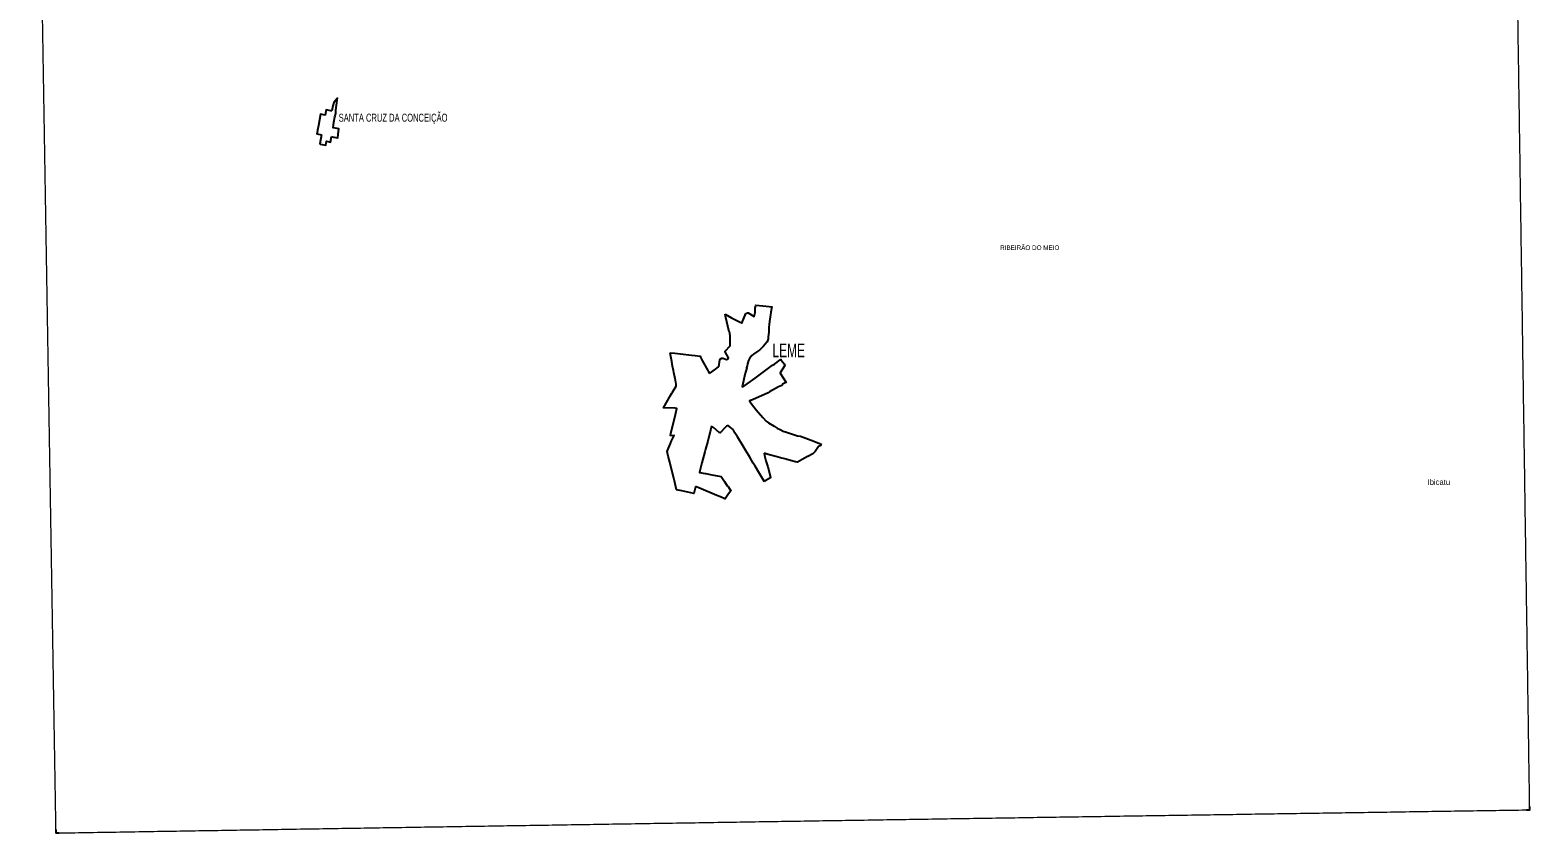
# Model space of a CAD drawing. Extents: x 241.9 to 268.1, y 7537.3 to 7565.4.
# Drawn here: x 241.88 to 268.11, y 7537.34 to 7551.39 of the extents above; entities that cross this region are included whole.
import ezdxf
from ezdxf.enums import TextEntityAlignment as Align

# ---------------------------------------------------------------- set-up
doc = ezdxf.new("R2010")
doc.units = 0
doc.header["$LTSCALE"] = 0.032
doc.linetypes.add('LONG_DASHED', pattern=[7.5, 6, -1.5])
for name, color, linetype, lineweight in [('41', 7, 'Continuous', 25), ('5', 7, 'LONG_DASHED', 13), ('63', 7, 'Continuous', 13)]:
    doc.layers.add(name, color=color, linetype=linetype, lineweight=lineweight)
doc.layers.add('61', color=7, linetype='Continuous')

msp = doc.modelspace()

# ---------------------------------------------------------------- linework, layer by layer
at = {"layer": '41'}
for points in [[(247.158, 7549.9711), (247.1423, 7549.9739), (247.0586, 7549.9889), (247.0416, 7549.8997), (246.9566, 7549.914), (246.9398, 7549.813), (246.9224, 7549.7189), (246.9078, 7549.6322), (246.9005, 7549.5936)], [(247.2292, 7549.9584), (247.2252, 7549.9827), (247.2514, 7550.157), (247.2544, 7550.1933), (247.1928, 7550.1205), (247.1731, 7550.0581), (247.158, 7549.9711)], [(247.2692, 7549.5651), (247.2766, 7549.6049), (247.2772, 7549.6582), (247.2513, 7549.6662), (247.1788, 7549.6778), (247.195, 7549.7748), (247.2115, 7549.8705)], [(247.2115, 7549.8705), (247.2261, 7549.9284), (247.2292, 7549.9584)], [(246.9005, 7549.5936), (246.897, 7549.5735), (246.9018, 7549.5702), (246.9774, 7549.556)], [(246.9774, 7549.556), (246.9477, 7549.3966), (246.9507, 7549.3926), (247.0543, 7549.3731), (247.0661, 7549.4409), (247.1354, 7549.4222), (247.1525, 7549.5231)], [(247.1525, 7549.5231), (247.1948, 7549.5152), (247.263, 7549.5023), (247.2692, 7549.5651)], [(253.9249, 7545.4932), (253.9436, 7545.6145), (253.9525, 7545.6292), (253.98, 7545.6484), (253.9977, 7545.6484), (254.0581, 7545.6246), (254.0845, 7545.6286), (254.0909, 7545.6366), (254.0933, 7545.6534), (254.0679, 7545.707), (254.0384, 7545.7591), (254.0375, 7545.7663), (254.1223, 7545.8648), (254.1272, 7545.8761), (254.1232, 7546.0246), (254.1173, 7546.0878), (254.1101, 7546.1062), (254.0421, 7546.3783), (254.0382, 7546.4182)], [(254.0382, 7546.4182), (254.1485, 7546.3511), (254.3125, 7546.2678), (254.328, 7546.2587), (254.3971, 7546.4281)], [(254.3971, 7546.4281), (254.4272, 7546.4389), (254.4378, 7546.4386), (254.5448, 7546.3759), (254.5648, 7546.4474)], [(254.5648, 7546.4474), (254.5621, 7546.4767), (254.5645, 7546.5191), (254.5756, 7546.5724), (254.6955, 7546.5598)], [(254.6955, 7546.5598), (254.8085, 7546.5479), (254.8557, 7546.5465), (254.8388, 7546.4513), (254.8303, 7546.4057)], [(254.8303, 7546.4057), (254.823, 7546.3706), (254.8178, 7546.3259), (254.8091, 7546.2404), (254.8036, 7546.1812), (254.7992, 7546.0986), (254.7899, 7546.0212)], [(254.7899, 7546.0212), (254.788, 7545.9853), (254.7797, 7545.947), (254.7701, 7545.9334), (254.7685, 7545.9238), (254.7077, 7545.8566), (254.6413, 7545.791), (254.6093, 7545.7662), (254.5349, 7545.7182), (254.5045, 7545.6926), (254.4645, 7545.6422), (254.4445, 7545.6038), (254.4261, 7545.5462), (254.4192, 7545.5146)], [(253.1383, 7545.3981), (253.1314, 7545.4308), (253.1187, 7545.5038), (253.1048, 7545.5855), (253.0838, 7545.7053), (253.0781, 7545.7416)], [(253.0781, 7545.7416), (253.1568, 7545.7362), (253.2542, 7545.7219), (253.4494, 7545.7017)], [(253.4494, 7545.7017), (253.5109, 7545.6953), (253.5974, 7545.6835), (253.6065, 7545.6637)], [(253.6065, 7545.6637), (253.6368, 7545.6058), (253.6586, 7545.5664), (253.7637, 7545.3763)], [(254.3395, 7545.1389), (254.5613, 7545.295), (254.8677, 7545.5222), (254.9005, 7545.5422), (254.9989, 7545.6158), (255.0061, 7545.6254), (255.0141, 7545.623), (255.0133, 7545.6198), (255.0531, 7545.5728), (255.0708, 7545.5453), (255.0806, 7545.5188), (254.9997, 7545.3918), (255.0013, 7545.383), (255.1031, 7545.2212), (255.0746, 7545.2094), (255.0392, 7545.1888), (255.0293, 7545.1694)], [(253.1052, 7545.0338), (253.118, 7545.0534), (253.178, 7545.159), (253.1812, 7545.1902), (253.178, 7545.1934), (253.1668, 7545.263), (253.1621, 7545.2851), (253.1383, 7545.3981)], [(253.7637, 7545.3763), (253.8666, 7545.4554), (253.9204, 7545.4926), (253.9249, 7545.4932)], [(254.4192, 7545.5146), (254.4113, 7545.4781), (254.4149, 7545.4766), (254.3821, 7545.3606), (254.3381, 7545.1686), (254.3373, 7545.1494), (254.3395, 7545.1389)], [(252.9799, 7544.8166), (253.066, 7544.9614), (253.0716, 7544.9774), (253.0885, 7545.0048), (253.1052, 7545.0338)], [(254.8117, 7545.059), (254.7905, 7545.0383), (254.5141, 7544.9182), (254.4611, 7544.8981), (254.4969, 7544.8468)], [(255.0293, 7545.1694), (254.9709, 7545.1422), (254.8117, 7545.059)], [(253.0799, 7544.2877), (253.0876, 7544.3349), (253.1579, 7544.6113), (253.1943, 7544.7686), (253.1609, 7544.7735), (252.9569, 7544.7768), (252.9799, 7544.8166)], [(254.4969, 7544.8468), (254.5805, 7544.7406), (254.6957, 7544.6086), (254.7573, 7544.5453), (254.7957, 7544.5149), (254.8963, 7544.4556)], [(253.022, 7544.0141), (253.0484, 7544.0717), (253.0791, 7544.1539), (253.1008, 7544.2001), (253.1473, 7544.2912), (253.0799, 7544.2877)], [(253.7963, 7544.4552), (253.7828, 7544.3877), (253.7324, 7544.1942), (253.691, 7544.0527)], [(254.1747, 7544.3994), (254.1041, 7544.4559), (254.0883, 7544.4608), (254.0765, 7544.4608), (254.0608, 7544.4554), (254.0441, 7544.4417), (253.9517, 7544.3421), (253.9349, 7544.3469), (253.8316, 7544.4309), (253.7963, 7544.4552)], [(254.5591, 7543.7561), (254.5277, 7543.8069), (254.4661, 7543.9157), (254.4484, 7543.9449), (254.3923, 7544.0379), (254.3495, 7544.1089), (254.2512, 7544.2717), (254.2091, 7544.3414), (254.1957, 7544.3636), (254.1747, 7544.3994)], [(254.8963, 7544.4556), (254.9462, 7544.4235), (255, 7544.4005)], [(255, 7544.4005), (255.0003, 7544.4004), (255.0544, 7544.3704), (255.1112, 7544.3529), (255.3045, 7544.2869)], [(255.3045, 7544.2869), (255.3529, 7544.2806), (255.5429, 7544.2141), (255.6758, 7544.1597), (255.691, 7544.1509), (255.6982, 7544.1501), (255.7118, 7544.1397), (255.715, 7544.1413), (255.6998, 7544.1117), (255.6701, 7544.1008), (255.6091, 7544.0154)], [(253.1885, 7543.3429), (253.1524, 7543.4981), (253.1488, 7543.5029), (253.1372, 7543.5498), (253.0925, 7543.7298), (253.0677, 7543.8294), (253.0426, 7543.9306), (253.022, 7544.0141)], [(253.691, 7544.0527), (253.6822, 7544.0059), (253.6296, 7543.8177)], [(255.3833, 7543.8726), (255.3027, 7543.8259), (255.2755, 7543.8305), (255.2622, 7543.8328), (255.2038, 7543.85), (255.1152, 7543.8751), (255.1028, 7543.8771), (255.0823, 7543.8831), (255.006, 7543.9048), (254.9253, 7543.9272), (254.7902, 7543.9639), (254.7191, 7543.9831)], [(254.7191, 7543.9831), (254.7277, 7543.9413), (254.7509, 7543.8517), (254.7837, 7543.7429), (254.8309, 7543.5669), (254.8301, 7543.5517), (254.7343, 7543.5028), (254.7225, 7543.4825)], [(255.6091, 7544.0154), (255.5964, 7543.9977), (255.5679, 7543.9736), (255.481, 7543.9283)], [(253.6296, 7543.8177), (253.594, 7543.6741), (253.5865, 7543.6458), (253.6846, 7543.6301)], [(254.7225, 7543.4825), (254.6197, 7543.6581), (254.5591, 7543.7561)], [(255.481, 7543.9283), (255.4784, 7543.9269), (255.3833, 7543.8726)], [(253.6846, 7543.6301), (253.7004, 7543.6261), (253.8032, 7543.6062), (253.9028, 7543.5896)], [(253.9028, 7543.5896), (253.9701, 7543.5784), (254.0255, 7543.4903), (254.0734, 7543.4142)], [(253.521, 7543.3991), (253.5196, 7543.3941), (253.4917, 7543.2772), (253.3861, 7543.3004), (253.2765, 7543.3245), (253.1885, 7543.3429)], [(254.0734, 7543.4142), (254.0915, 7543.403), (254.1269, 7543.3445), (254.1301, 7543.3437), (254.1341, 7543.3261), (254.0957, 7543.2757), (254.0363, 7543.1872), (254.0304, 7543.1867), (253.9557, 7543.2189), (253.8898, 7543.2424), (253.5748, 7543.3789), (253.521, 7543.3991)]]:
    msp.add_lwpolyline(points, dxfattribs=at)
at = {"layer": '5'}
for p, q in [((254.3971, 7546.4281), (254.328, 7546.2587)), ((254.8557, 7546.5465), (254.8388, 7546.4513))]:
    msp.add_line(p, q, dxfattribs=at)
msp.add_lwpolyline([(254.5448, 7546.3759), (254.4378, 7546.4386), (254.4272, 7546.4389), (254.3971, 7546.4281)], dxfattribs=at)
at = {"layer": '63', "lineweight": 25}
for points in [[(268.0533, 7537.7446), (268.1149, 7537.7446), (268.1149, 7537.8053)], [(242.3278, 7537.403), (242.3278, 7537.3414), (242.3885, 7537.3414)]]:
    msp.add_lwpolyline(points, dxfattribs=at)
at = {"layer": '63'}
for points in [[(268.1099, 7537.7446), (268.1015, 7538.3096), (268.0931, 7538.8747), (268.0847, 7539.4398), (268.0763, 7540.0048), (268.0679, 7540.5699), (268.0595, 7541.135), (268.0511, 7541.7), (268.0427, 7542.2651), (268.0343, 7542.8301), (268.0259, 7543.3952), (268.0176, 7543.9603), (268.0092, 7544.5253), (268.0008, 7545.0904), (267.9924, 7545.6554), (267.984, 7546.2205), (267.9757, 7546.7856), (267.9673, 7547.3506), (267.9589, 7547.9157), (267.9505, 7548.4807), (267.9422, 7549.0458), (267.9338, 7549.6109), (267.9254, 7550.1759), (267.9171, 7550.741), (267.9087, 7551.306), (267.9003, 7551.8711), (267.892, 7552.4361), (267.8836, 7553.0012), (267.8753, 7553.5663), (267.8669, 7554.1313), (267.8586, 7554.6964), (267.8502, 7555.2614), (267.8419, 7555.8265), (267.8335, 7556.3915), (267.8252, 7556.9566), (267.8168, 7557.5216), (267.8085, 7558.0867), (267.8001, 7558.6517), (267.7918, 7559.2168), (267.7835, 7559.7818), (267.7751, 7560.3469), (267.7668, 7560.9119), (267.7585, 7561.477), (267.7501, 7562.0421), (267.7418, 7562.6071), (267.7335, 7563.1722), (267.7252, 7563.7372), (267.7168, 7564.3023), (267.7085, 7564.8673), (267.7002, 7565.4324)], [(242.3332, 7537.3398), (242.3239, 7537.9049), (242.3145, 7538.47), (242.3052, 7539.0352), (242.2958, 7539.6003), (242.2865, 7540.1654), (242.2772, 7540.7306), (242.2679, 7541.2957), (242.2585, 7541.8608), (242.2492, 7542.426), (242.2399, 7542.9911), (242.2306, 7543.5563), (242.2212, 7544.1214), (242.2119, 7544.6865), (242.2026, 7545.2517), (242.1933, 7545.8168), (242.184, 7546.3819), (242.1747, 7546.9471), (242.1654, 7547.5122), (242.1561, 7548.0773), (242.1468, 7548.6425), (242.1375, 7549.2076), (242.1282, 7549.7727), (242.1189, 7550.3378), (242.1096, 7550.903), (242.1003, 7551.4681), (242.091, 7552.0332), (242.0817, 7552.5984), (242.0724, 7553.1635), (242.0631, 7553.7286), (242.0538, 7554.2938), (242.0446, 7554.8589), (242.0353, 7555.424), (242.026, 7555.9891), (242.0167, 7556.5543), (242.0074, 7557.1194), (241.9982, 7557.6845), (241.9889, 7558.2496), (241.9796, 7558.8148), (241.9704, 7559.3799), (241.9611, 7559.945), (241.9519, 7560.5102), (241.9426, 7561.0753), (241.9333, 7561.6404), (241.9241, 7562.2055), (241.9148, 7562.7707), (241.9056, 7563.3358), (241.8963, 7563.9009), (241.8871, 7564.466), (241.8778, 7565.0311)], [(242.3332, 7537.3398), (242.8593, 7537.3484), (243.3854, 7537.3571), (243.9115, 7537.3658), (244.4376, 7537.3744), (244.9636, 7537.383), (245.4897, 7537.3916), (246.0158, 7537.4002), (246.5419, 7537.4088), (247.068, 7537.4173), (247.594, 7537.4258), (248.1201, 7537.4344), (248.6462, 7537.4428), (249.1723, 7537.4513), (249.6983, 7537.4598), (250.2244, 7537.4682), (250.7505, 7537.4766), (251.2765, 7537.485), (251.8026, 7537.4934), (252.3287, 7537.5018), (252.8547, 7537.5101), (253.3808, 7537.5185), (253.9068, 7537.5268), (254.4329, 7537.5351), (254.959, 7537.5434), (255.485, 7537.5516), (256.0111, 7537.5599), (256.5371, 7537.5681), (257.0632, 7537.5763), (257.5892, 7537.5845), (258.1153, 7537.5927), (258.6413, 7537.6008), (259.1674, 7537.609), (259.6934, 7537.6171), (260.2194, 7537.6252), (260.7455, 7537.6333), (261.2715, 7537.6413), (261.7976, 7537.6494), (262.3236, 7537.6574), (262.8496, 7537.6654), (263.3757, 7537.6734), (263.9017, 7537.6814), (264.4277, 7537.6894), (264.9538, 7537.6973), (265.4798, 7537.7052), (266.0058, 7537.7131), (266.5319, 7537.721), (267.0579, 7537.7289), (267.5839, 7537.7367), (268.1099, 7537.7446)]]:
    msp.add_spline(points, degree=3, dxfattribs=at)

# ---------------------------------------------------------------- texts
at = {"layer": '61', "width": 0.65}
for s, height, p in [('SANTA CRUZ DA CONCEIÇÃO', 0.14, (247.2772, 7549.7833)), ('LEME', 0.24, (254.8646, 7545.6611))]:
    msp.add_text(s, height=height, dxfattribs=at).set_placement(p)
at = {"layer": '61', "width": 0.95}
msp.add_text('RIBEIRÃO DO MEIO', height=0.08, dxfattribs=at).set_placement((259.3652, 7547.5391), align=Align.CENTER)
at = {"layer": '61'}
msp.add_text('Ibicatu', height=0.1, dxfattribs=at).set_placement((266.3239, 7543.4291))

doc.saveas('drawing.dxf')
